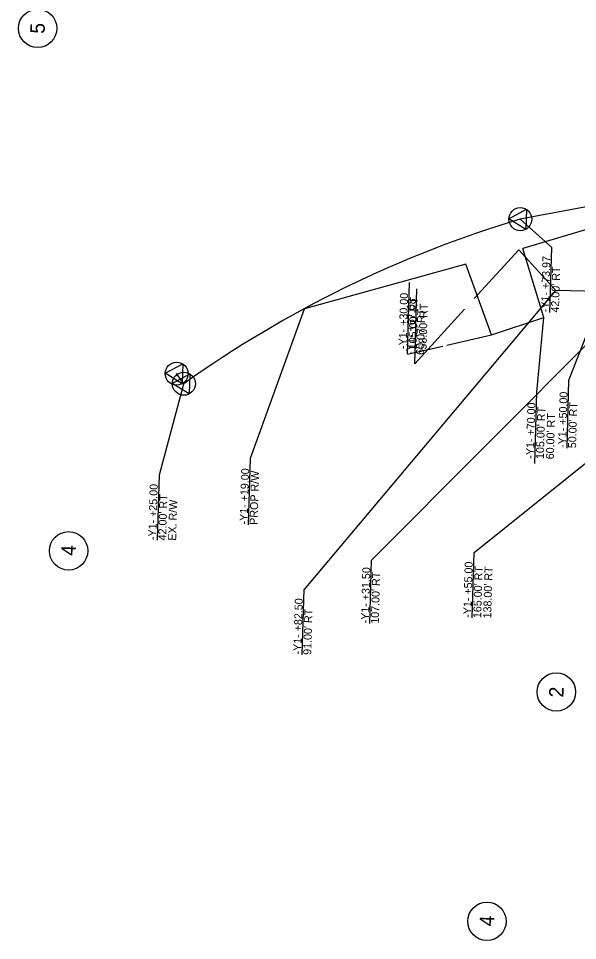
# Model space of a CAD drawing. Extents: x 2097272 to 2098144, y 685104 to 689282.
# Drawn here: x 2097272 to 2097622, y 685351 to 685927 of the extents above; entities that cross this region are included whole.
import ezdxf

# ---------------------------------------------------------------- set-up
doc = ezdxf.new("R2010")
doc.units = 0
for name, color, linetype in [('Prop Easement Construction', 7, 'Continuous'), ('Prop Easement Construction Station Offsets', 7, 'Continuous'), ('Prop Parcel Number CELL', 7, 'Continuous'), ('Prop ROW Marker CELL', 7, 'Continuous'), ('Prop ROW RW Lines', 7, 'Continuous'), ('Prop ROW Station Offsets', 7, 'Continuous'), ('Scratch_Level_6', 7, 'Continuous')]:
    doc.layers.add(name, color=color, linetype=linetype)

msp = doc.modelspace()

# ---------------------------------------------------------------- linework, layer by layer
at = {"layer": 'Prop Easement Construction'}
for p, q in [((2097660.04, 685804.9), (2097587.39, 685783.15)), ((2097600.52, 685740.11), (2097587.39, 685783.15)), ((2097551.77, 685773.36), (2097450.71, 685745.52)), ((2097567.82, 685729.19), (2097551.77, 685773.36)), ((2097567.82, 685729.19), (2097600.52, 685740.11))]:
    msp.add_line(p, q, dxfattribs=at)
at = {"layer": 'Prop Easement Construction Station Offsets'}
for p, q in [((2097515.12, 685717.26), (2097516.41, 685761.91)), ((2097417.03, 685652.25), (2097450.71, 685745.52)), ((2097596.04, 685693.39), (2097600.52, 685740.11)), ((2097539.84, 685722.73), (2097567.82, 685729.19)), ((2097515.11, 685717.03), (2097537.2, 685722.12)), ((2097594.74, 685648.74), (2097596.04, 685693.39)), ((2097415.82, 685610.6), (2097417.03, 685652.25))]:
    msp.add_line(p, q, dxfattribs=at)
at = {"layer": 'Prop Parcel Number CELL'}
for centre in [(2097283.93, 685920.62), (2097303.29, 685594.26), (2097608.27, 685506.12), (2097564.88, 685362.82)]:
    msp.add_circle(centre, 12, dxfattribs=at)
at = {"layer": 'Prop ROW Marker CELL'}
for p, q in [((2097585.74, 685801.45), (2097585.74, 685801.45)), ((2097370.86, 685704.96), (2097370.86, 685704.96)), ((2097375.35, 685698.65), (2097375.35, 685698.65))]:
    msp.add_line(p, q, dxfattribs=at)
for points in [[(2097589.15, 685795.1), (2097578.54, 685801.66), (2097589.52, 685807.6)], [(2097374.28, 685698.61), (2097363.66, 685705.17), (2097374.64, 685711.1)], [(2097378.76, 685692.3), (2097368.15, 685698.86), (2097379.13, 685704.79)]]:
    msp.add_lwpolyline(points, close=True, dxfattribs=at)
for centre in [(2097585.74, 685801.45), (2097370.86, 685704.96), (2097375.35, 685698.65)]:
    msp.add_circle(centre, 7.2, dxfattribs=at)
at = {"layer": 'Prop ROW RW Lines'}
for p, q in [((2097660.87, 685815.58), (2097585.74, 685801.45)), ((2097375.35, 685698.65), (2097370.86, 685704.96))]:
    msp.add_line(p, q, dxfattribs=at)
msp.add_arc((2097791.55, 685113.58), 718, 106.65716, 125.42709, dxfattribs=at)
at = {"layer": 'Prop ROW Station Offsets'}
for p, q in [((2097616.18, 685700.94), (2097660.87, 685815.58)), ((2097605.41, 685783.75), (2097585.74, 685801.45)), ((2097604.23, 685743.22), (2097605.41, 685783.75)), ((2097614.95, 685658.47), (2097616.18, 685700.94)), ((2097360.06, 685641.77), (2097375.35, 685698.65)), ((2097358.88, 685600.88), (2097360.06, 685641.77))]:
    msp.add_line(p, q, dxfattribs=at)
at = {"layer": 'Scratch_Level_6'}
for p, q in [((2097556.95, 685751.8), (2097584.85, 685782.29)), ((2097607.95, 685756.95), (2097584.85, 685782.29)), ((2097519.73, 685711.13), (2097521.09, 685757.88)), ((2097450.53, 685569.88), (2097607.95, 685756.95)), ((2097492.76, 685588.34), (2097659.48, 685755.67)), ((2097659.48, 685755.67), (2097607.95, 685756.95)), ((2097519.73, 685711.13), (2097550.93, 685745.23)), ((2097556.81, 685593.22), (2097698.62, 685706.84)), ((2097555.62, 685552.33), (2097556.81, 685593.22)), ((2097491.61, 685548.81), (2097492.76, 685588.34)), ((2097449.35, 685529.4), (2097450.54, 685570.29))]:
    msp.add_line(p, q, dxfattribs=at)

# ---------------------------------------------------------------- texts
at = {"layer": 'Prop Easement Construction Station Offsets'}
for s, p in [('-Y1- +30.00', (2097514.58, 685720.27)), ("105.00' RT", (2097520.82, 685720.09)), ("58.00' RT", (2097527.07, 685719.91)), ('-Y1- +70.00', (2097594.21, 685651.75)), ("105.00' RT", (2097600.45, 685651.57)), ("60.00' RT", (2097606.7, 685651.39)), ('-Y1- +19.00', (2097415.19, 685610.62)), ('PROP R/W', (2097421.44, 685610.44))]:
    msp.add_text(s, height=5, rotation=88.33483, dxfattribs=at).set_placement(p)
at = {"layer": 'Prop Parcel Number CELL'}
for s, p in [('5', (2097288.33, 685917.2)), ('4', (2097307.7, 685591.08)), ('2', (2097612.67, 685502.56)), ('4', (2097569.29, 685359.65))]:
    msp.add_text(s, height=9, rotation=88.33483, dxfattribs=at).set_placement(p)
at = {"layer": 'Prop ROW Station Offsets'}
for s, p in [('-Y1- +73.97', (2097603.61, 685743.24)), ("42.00' RT", (2097609.86, 685743.06)), ('-Y1- +50.00', (2097614.32, 685658.49)), ("50.00' RT", (2097620.57, 685658.31)), ('-Y1- +25.00', (2097358.03, 685600.91)), ("42.00' RT", (2097364.27, 685600.73)), ('EX. R/W', (2097370.52, 685600.55))]:
    msp.add_text(s, height=5, rotation=88.33483, dxfattribs=at).set_placement(p)
at = {"layer": 'Scratch_Level_6'}
for s, p in [('-Y1- +67.08', (2097519.27, 685716.8)), ("60.07' RT", (2097525.52, 685716.62)), ('-Y1- +55.00', (2097555, 685552.35)), ('-Y1- +31.50', (2097490.99, 685548.83)), ("107.00' RT", (2097497.23, 685548.65)), ("165.00' RT", (2097561.25, 685552.17)), ("138.00' RT", (2097567.49, 685551.98)), ('-Y1- +82.50', (2097448.73, 685529.42)), ("91.00' RT", (2097454.98, 685529.24))]:
    msp.add_text(s, height=5, rotation=88.33483, dxfattribs=at).set_placement(p)

doc.saveas('drawing.dxf')
